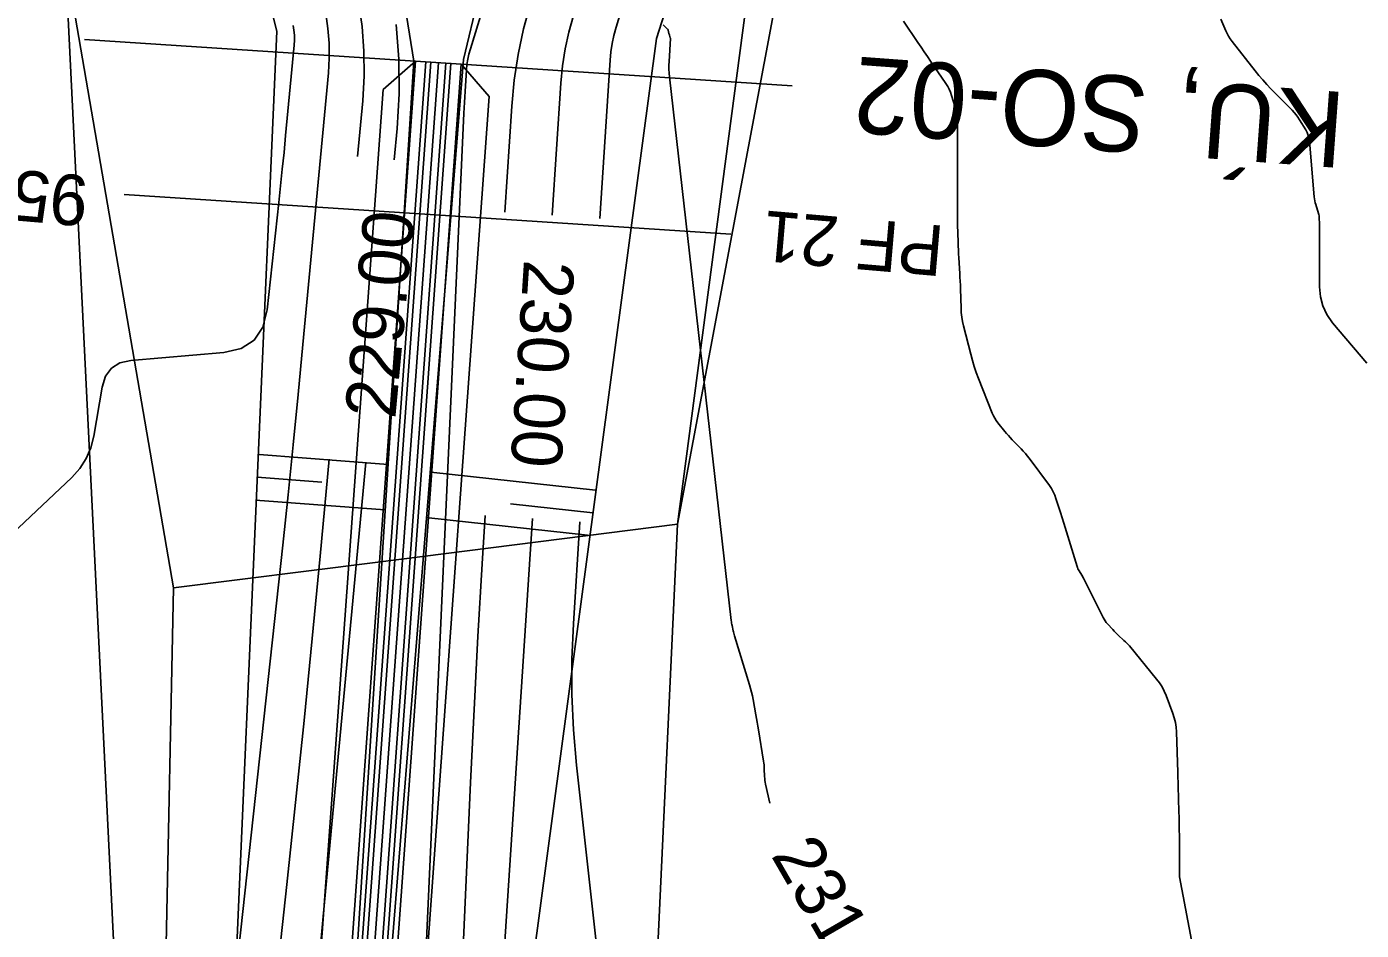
# Model space of a CAD drawing. Extents: x -534410 to -534262, y -1190162 to -1189584.
# Drawn here: x -534369.46 to -534343.12, y -1189644.95 to -1189627.11 of the extents above; entities that cross this region are included whole.
import ezdxf

# ---------------------------------------------------------------- set-up
doc = ezdxf.new("R2010")
doc.units = 0
for name, color, linetype in [('30', 7, 'Continuous'), ('31', 7, 'Continuous'), ('40', 7, 'Continuous'), ('_linie', 7, 'Continuous'), ('_N_osa', 7, 'Continuous'), ('_N_tenká', 7, 'Continuous'), ('_N_tenká_velmi', 7, 'Continuous'), ('_N_text', 7, 'Continuous'), ('_tenka', 7, 'Continuous'), ('_velmi_tenka', 7, 'Continuous'), ('Default', 7, 'Continuous'), ('Hranice parcel', 7, 'Continuous')]:
    doc.layers.add(name, color=color, linetype=linetype)

msp = doc.modelspace()

# ---------------------------------------------------------------- linework, layer by layer
at = {"layer": '30'}
for points in [[(-534357.514, -1189620.943), (-534357.514, -1189620.944), (-534357.5, -1189620.975), (-534357.487, -1189621.008), (-534357.44, -1189621.138), (-534357.431, -1189621.171), (-534357.426, -1189621.204), (-534357.425, -1189621.237), (-534357.429, -1189621.271), (-534357.952, -1189624.26), (-534358.016, -1189624.595), (-534358.09, -1189624.928), (-534358.175, -1189625.258), (-534358.27, -1189625.585), (-534358.669, -1189626.89), (-534358.759, -1189627.218), (-534358.83, -1189627.55), (-534358.881, -1189627.885), (-534358.913, -1189628.224), (-534359.084, -1189630.834)], [(-534361.638, -1189646.761), (-534360.829, -1189628.817), (-534360.824, -1189628.711), (-534360.819, -1189628.604), (-534360.813, -1189628.497), (-534360.806, -1189628.391), (-534360.778, -1189627.965), (-534360.768, -1189627.859), (-534360.752, -1189627.754), (-534360.73, -1189627.65), (-534360.702, -1189627.547), (-534359.197, -1189622.632)], [(-534365.316, -1189645.725), (-534364.406, -1189637.346), (-534364.301, -1189636.356), (-534364.199, -1189635.366), (-534364.1, -1189634.375), (-534364.006, -1189633.383), (-534363.504, -1189628.024), (-534363.486, -1189627.729), (-534363.489, -1189627.436), (-534363.512, -1189627.143), (-534363.555, -1189626.851)], [(-534362.168, -1189627.067), (-534362.114, -1189627.75), (-534362.108, -1189628.435), (-534362.149, -1189629.123), (-534362.207, -1189629.742)], [(-534356.898, -1189627.07), (-534356.802, -1189627.166), (-534356.799, -1189627.168), (-534356.797, -1189627.171), (-534356.796, -1189627.174), (-534356.795, -1189627.178), (-534356.783, -1189627.244), (-534356.781, -1189627.25), (-534356.779, -1189627.255), (-534356.773, -1189627.268), (-534356.771, -1189627.276), (-534356.755, -1189627.329), (-534356.754, -1189627.334), (-534356.753, -1189627.34), (-534356.779, -1189627.795), (-534356.781, -1189627.872), (-534356.781, -1189627.949), (-534356.777, -1189628.025), (-534356.77, -1189628.102), (-534355.551, -1189638.836), (-534355.548, -1189638.861), (-534355.544, -1189638.886), (-534355.54, -1189638.911), (-534355.534, -1189638.936), (-534355.512, -1189639.036), (-534355.507, -1189639.061), (-534355.5, -1189639.086), (-534355.494, -1189639.111), (-534355.486, -1189639.135), (-534355.19, -1189640.102), (-534355.169, -1189640.175), (-534355.15, -1189640.248), (-534355.134, -1189640.322), (-534355.119, -1189640.397), (-534355.066, -1189640.695), (-534355.053, -1189640.77), (-534355.04, -1189640.845), (-534355.028, -1189640.919), (-534355.015, -1189640.994), (-534354.914, -1189641.61), (-534354.909, -1189641.648), (-534354.904, -1189641.686), (-534354.901, -1189641.724), (-534354.899, -1189641.762), (-534354.893, -1189641.915), (-534354.891, -1189641.953), (-534354.887, -1189641.991), (-534354.881, -1189642.029), (-534354.874, -1189642.066), (-534354.791, -1189642.439)], [(-534343.005, -1189633.752), (-534343.681, -1189632.954), (-534343.794, -1189632.795), (-534343.875, -1189632.624), (-534343.924, -1189632.441), (-534343.94, -1189632.246), (-534343.94, -1189631.091), (-534343.94, -1189631.066), (-534343.941, -1189631.042), (-534343.941, -1189631.017), (-534343.942, -1189630.992), (-534343.945, -1189630.894), (-534343.947, -1189630.869), (-534343.95, -1189630.845), (-534343.955, -1189630.821), (-534343.961, -1189630.797), (-534344.015, -1189630.623), (-534344.026, -1189630.586), (-534344.034, -1189630.548), (-534344.041, -1189630.511), (-534344.045, -1189630.472), (-534344.14, -1189629.37), (-534344.148, -1189629.312), (-534344.163, -1189629.255), (-534344.184, -1189629.201), (-534344.212, -1189629.149), (-534344.336, -1189628.946), (-534344.369, -1189628.896), (-534344.404, -1189628.849), (-534344.442, -1189628.803), (-534344.482, -1189628.76), (-534344.899, -1189628.336), (-534344.981, -1189628.25), (-534345.06, -1189628.162), (-534345.137, -1189628.072), (-534345.212, -1189627.98), (-534345.666, -1189627.402), (-534345.703, -1189627.352), (-534345.736, -1189627.3), (-534345.765, -1189627.245), (-534345.791, -1189627.189), (-534345.887, -1189626.959)], [(-534362.766, -1189635.716), (-534363.58, -1189644.397), (-534363.668, -1189645.326), (-534363.76, -1189646.254), (-534363.856, -1189647.182), (-534363.955, -1189648.109), (-534364.357, -1189651.819), (-534364.456, -1189652.746), (-534364.55, -1189653.674), (-534364.64, -1189654.602), (-534364.726, -1189655.531), (-534365.346, -1189662.432), (-534365.472, -1189663.892), (-534365.591, -1189665.352), (-534365.7, -1189666.814), (-534365.801, -1189668.276), (-534366.596, -1189680.297)], [(-534359.474, -1189636.822), (-534360.283, -1189649.202)]]:
    msp.add_lwpolyline(points, dxfattribs=at)
at = {"layer": '31'}
for points in [[(-534358.147, -1189630.895), (-534357.942, -1189627.768), (-534357.927, -1189627.604), (-534357.902, -1189627.442), (-534357.868, -1189627.281), (-534357.824, -1189627.122), (-534357.631, -1189626.49), (-534357.585, -1189626.331), (-534357.544, -1189626.171), (-534357.508, -1189626.01), (-534357.477, -1189625.848), (-534356.628, -1189621), (-534356.625, -1189620.976), (-534356.626, -1189620.953), (-534356.629, -1189620.929), (-534356.636, -1189620.907), (-534356.669, -1189620.816), (-534356.678, -1189620.793), (-534356.687, -1189620.771), (-534356.688, -1189620.771)], [(-534362.929, -1189629.674), (-534362.826, -1189628.573), (-534362.797, -1189628.082), (-534362.802, -1189627.593), (-534362.84, -1189627.105), (-534362.912, -1189626.619), (-534363.334, -1189624.309), (-534363.39, -1189624.007), (-534363.45, -1189623.706), (-534363.512, -1189623.405), (-534363.576, -1189623.105), (-534363.953, -1189621.395), (-534363.959, -1189621.351), (-534363.959, -1189621.308), (-534363.952, -1189621.265), (-534363.938, -1189621.222), (-534363.868, -1189621.054), (-534363.848, -1189621.013), (-534363.826, -1189620.975), (-534363.823, -1189620.971)], [(-534358.341, -1189621.116), (-534358.34, -1189621.117), (-534358.322, -1189621.158), (-534358.306, -1189621.2), (-534358.245, -1189621.369), (-534358.232, -1189621.412), (-534358.226, -1189621.455), (-534358.225, -1189621.498), (-534358.23, -1189621.542), (-534358.508, -1189623.132), (-534358.561, -1189623.411), (-534358.623, -1189623.687), (-534358.693, -1189623.962), (-534358.772, -1189624.235), (-534359.514, -1189626.658), (-534359.65, -1189627.155), (-534359.758, -1189627.658), (-534359.835, -1189628.166), (-534359.884, -1189628.679), (-534360.021, -1189630.773)], [(-534364.198, -1189627.084), (-534364.184, -1189627.181), (-534364.176, -1189627.279), (-534364.175, -1189627.376), (-534364.181, -1189627.475), (-534364.349, -1189629.261), (-534364.38, -1189629.592), (-534364.413, -1189629.922), (-534364.447, -1189630.252), (-534364.482, -1189630.582), (-534364.712, -1189632.702), (-534364.797, -1189633.044), (-534364.968, -1189633.297), (-534365.226, -1189633.463), (-534365.569, -1189633.541), (-534367.402, -1189633.701), (-534367.62, -1189633.749), (-534367.788, -1189633.853), (-534367.905, -1189634.012), (-534367.971, -1189634.226), (-534368.133, -1189635.192), (-534368.19, -1189635.425), (-534368.283, -1189635.639), (-534368.409, -1189635.834), (-534368.571, -1189636.011), (-534371.025, -1189638.319)], [(-534346.466, -1189645.149), (-534346.704, -1189643.898), (-534346.706, -1189643.889), (-534346.707, -1189643.88), (-534346.707, -1189643.871), (-534346.707, -1189643.862), (-534346.707, -1189643.791), (-534346.707, -1189643.086), (-534346.708, -1189642.965), (-534346.709, -1189642.845), (-534346.712, -1189642.724), (-534346.715, -1189642.604), (-534346.738, -1189641.853), (-534346.738, -1189641.836), (-534346.764, -1189641.033), (-534346.771, -1189640.94), (-534346.785, -1189640.847), (-534346.807, -1189640.757), (-534346.836, -1189640.668), (-534346.969, -1189640.314), (-534347.006, -1189640.227), (-534347.049, -1189640.145), (-534347.099, -1189640.066), (-534347.156, -1189639.991), (-534347.694, -1189639.337), (-534347.719, -1189639.308), (-534347.745, -1189639.28), (-534347.772, -1189639.253), (-534347.8, -1189639.226), (-534347.913, -1189639.123), (-534347.942, -1189639.097), (-534347.969, -1189639.07), (-534347.996, -1189639.043), (-534348.022, -1189639.015), (-534348.125, -1189638.901), (-534348.149, -1189638.872), (-534348.172, -1189638.842), (-534348.192, -1189638.809), (-534348.211, -1189638.776), (-534348.587, -1189638.023), (-534348.598, -1189638.001), (-534348.609, -1189637.98), (-534348.622, -1189637.958), (-534348.634, -1189637.938), (-534348.685, -1189637.854), (-534348.698, -1189637.833), (-534348.708, -1189637.811), (-534348.718, -1189637.789), (-534348.726, -1189637.766), (-534348.99, -1189636.914), (-534349.055, -1189636.705), (-534349.142, -1189636.426), (-534349.166, -1189636.358), (-534349.196, -1189636.292), (-534349.231, -1189636.229), (-534349.272, -1189636.169), (-534349.671, -1189635.629), (-534349.708, -1189635.581), (-534349.746, -1189635.534), (-534349.787, -1189635.489), (-534349.828, -1189635.445), (-534350.007, -1189635.264), (-534350.045, -1189635.224), (-534350.082, -1189635.184), (-534350.118, -1189635.143), (-534350.153, -1189635.1), (-534350.29, -1189634.93), (-534350.323, -1189634.886), (-534350.352, -1189634.84), (-534350.377, -1189634.793), (-534350.399, -1189634.743), (-534350.67, -1189634.059), (-534350.715, -1189633.941), (-534350.756, -1189633.822), (-534350.793, -1189633.701), (-534350.826, -1189633.579), (-534350.968, -1189633.017), (-534350.988, -1189632.93), (-534351.002, -1189632.843), (-534351.012, -1189632.755), (-534351.017, -1189632.667), (-534351.028, -1189632.288), (-534351.03, -1189632.211), (-534351.033, -1189632.134), (-534351.037, -1189632.057), (-534351.041, -1189631.98), (-534351.059, -1189631.673), (-534351.064, -1189631.596), (-534351.067, -1189631.519), (-534351.07, -1189631.442), (-534351.073, -1189631.365), (-534351.084, -1189631.013), (-534351.086, -1189630.929), (-534351.088, -1189630.844), (-534351.089, -1189630.76), (-534351.089, -1189630.676), (-534351.089, -1189628.976), (-534351.091, -1189628.911), (-534351.098, -1189628.846), (-534351.11, -1189628.782), (-534351.127, -1189628.719), (-534351.202, -1189628.467), (-534351.223, -1189628.405), (-534351.249, -1189628.345), (-534351.279, -1189628.288), (-534351.314, -1189628.233), (-534351.617, -1189627.792), (-534351.68, -1189627.7), (-534351.743, -1189627.609), (-534351.805, -1189627.517), (-534351.867, -1189627.425), (-534352.15, -1189627.003)], [(-534365.291, -1189652.963), (-534364.324, -1189644.049), (-534364.151, -1189642.43), (-534363.984, -1189640.809), (-534363.824, -1189639.189), (-534363.669, -1189637.567), (-534363.489, -1189635.648)], [(-534360.41, -1189636.76), (-534360.47, -1189637.715), (-534360.553, -1189639.153), (-534360.629, -1189640.593), (-534360.697, -1189642.032), (-534361.011, -1189648.981), (-534361.079, -1189650.619), (-534361.135, -1189652.258), (-534361.181, -1189653.897), (-534361.215, -1189655.536), (-534361.422, -1189667.638), (-534361.413, -1189668.597), (-534361.351, -1189669.551), (-534361.238, -1189670.5), (-534361.072, -1189671.445), (-534359.975, -1189676.838)], [(-534358.205, -1189645.301), (-534358.606, -1189641.691), (-534358.668, -1189640.994), (-534358.699, -1189640.296), (-534358.699, -1189639.597), (-534358.669, -1189638.898), (-534358.538, -1189636.883)]]:
    msp.add_lwpolyline(points, dxfattribs=at)
at = {"layer": '_linie'}
for points in [[(-534366.12, -1189620.81), (-534364.52, -1189627.2), (-534365.69, -1189653.8), (-534366.76, -1189684.81), (-534368.14, -1189748.73), (-534368.38, -1189779.14), (-534368.65, -1189820.64), (-534368.59, -1189847.58), (-534367.2, -1189913.8)], [(-534363.12, -1189621.02), (-534362.79, -1189621.58), (-534361.82, -1189627.79), (-534363.46, -1189653.55), (-534365.47, -1189684.77), (-534366.65, -1189748.83), (-534366.75, -1189779.47), (-534366.9, -1189820.47), (-534366.95, -1189846.72), (-534366.338, -1189888.804), (-534363.85, -1189911.95), (-534357.07, -1189929.19), (-534352.334, -1189940.856)], [(-534359.03, -1189621.26), (-534359.41, -1189621.83), (-534360.84, -1189627.76), (-534362.92, -1189653.56), (-534364.64, -1189685), (-534365.94, -1189748.9), (-534366.02, -1189779.52), (-534366.03, -1189820.5), (-534366.48, -1189846.73), (-534365.511, -1189888.873), (-534362.72, -1189912.12), (-534356.62, -1189928.64), (-534351.589, -1189940.594)]]:
    msp.add_lwpolyline(points, dxfattribs=at)
at = {"layer": '_N_osa'}
msp.add_lwpolyline([(-534351.95, -1189940.722), (-534356.845, -1189928.915), (-534363.285, -1189912.035), (-534365.925, -1189888.838), (-534366.715, -1189846.725), (-534366.465, -1189820.485), (-534366.385, -1189779.495), (-534366.295, -1189748.865), (-534365.055, -1189684.885), (-534363.19, -1189653.555), (-534361.333, -1189627.822)], dxfattribs=at)
at = {"layer": '_N_tenká'}
msp.add_line((-534354.347, -1189628.277), (-534368.317, -1189627.366), dxfattribs=at)
for points in [[(-534352.92, -1189941.124), (-534357.821, -1189929.303), (-534364.313, -1189912.285), (-534366.973, -1189888.908), (-534367.765, -1189846.73), (-534367.515, -1189820.479), (-534367.435, -1189779.492), (-534367.345, -1189748.853), (-534366.104, -1189684.844), (-534364.238, -1189653.486), (-534362.424, -1189628.352), (-534361.782, -1189627.792)], [(-534352.089, -1189940.779), (-534356.984, -1189928.97), (-534363.432, -1189912.071), (-534366.074, -1189888.848), (-534366.865, -1189846.726), (-534366.615, -1189820.484), (-534366.535, -1189779.495), (-534366.445, -1189748.863), (-534365.205, -1189684.879), (-534363.34, -1189653.545), (-534361.483, -1189627.812)], [(-534351.812, -1189940.664), (-534356.706, -1189928.86), (-534363.138, -1189911.999), (-534365.775, -1189888.828), (-534366.565, -1189846.724), (-534366.315, -1189820.486), (-534366.235, -1189779.495), (-534366.145, -1189748.867), (-534364.905, -1189684.891), (-534363.04, -1189653.565), (-534361.184, -1189627.831)], [(-534350.98, -1189940.319), (-534355.869, -1189928.527), (-534362.257, -1189911.785), (-534364.876, -1189888.769), (-534365.665, -1189846.72), (-534365.415, -1189820.491), (-534365.335, -1189779.498), (-534365.245, -1189748.877), (-534364.006, -1189684.926), (-534362.142, -1189653.624), (-534360.329, -1189628.488), (-534360.884, -1189627.851)]]:
    msp.add_lwpolyline(points, dxfattribs=at)
at = {"layer": '_N_tenká_velmi'}
for points in [[(-534352.366, -1189940.894), (-534357.263, -1189929.081), (-534363.726, -1189912.142), (-534366.374, -1189888.868), (-534367.165, -1189846.727), (-534366.915, -1189820.482), (-534366.835, -1189779.494), (-534366.745, -1189748.86), (-534365.505, -1189684.867), (-534363.639, -1189653.525), (-534361.782, -1189627.792)], [(-534352.181, -1189940.817), (-534357.077, -1189929.007), (-534363.53, -1189912.095), (-534366.174, -1189888.855), (-534366.965, -1189846.726), (-534366.715, -1189820.484), (-534366.635, -1189779.494), (-534366.545, -1189748.862), (-534365.305, -1189684.875), (-534363.439, -1189653.539), (-534361.583, -1189627.805)], [(-534351.719, -1189940.626), (-534356.613, -1189928.823), (-534363.04, -1189911.975), (-534365.675, -1189888.822), (-534366.465, -1189846.724), (-534366.215, -1189820.486), (-534366.135, -1189779.496), (-534366.045, -1189748.868), (-534364.805, -1189684.895), (-534362.941, -1189653.571), (-534361.084, -1189627.838)], [(-534351.534, -1189940.549), (-534356.427, -1189928.749), (-534362.844, -1189911.928), (-534365.475, -1189888.808), (-534366.265, -1189846.723), (-534366.015, -1189820.488), (-534365.935, -1189779.496), (-534365.845, -1189748.87), (-534364.605, -1189684.903), (-534362.741, -1189653.585), (-534360.884, -1189627.851)]]:
    msp.add_lwpolyline(points, dxfattribs=at)
at = {"layer": '_N_text'}
msp.add_lwpolyline([(-534355.562, -1189631.204), (-534367.537, -1189630.423)], dxfattribs=at)
at = {"layer": '_tenka'}
for points in [[(-534349.13, -1189939.73), (-534354.63, -1189926.96), (-534362.03, -1189907.65), (-534364.521, -1189888.74), (-534364.47, -1189846.64), (-534364.29, -1189820.63), (-534364.22, -1189780.69), (-534363.18, -1189749.38), (-534362.5, -1189685.39), (-534360.27, -1189651.6), (-534357.03, -1189627.34), (-534354.77, -1189620.37)], [(-534366.12, -1189620.81), (-534364.52, -1189627.2), (-534365.69, -1189653.8), (-534366.76, -1189684.81), (-534368.14, -1189748.73), (-534368.38, -1189779.14), (-534368.65, -1189820.64), (-534368.59, -1189847.58), (-534367.2, -1189913.8)], [(-534366.12, -1189620.81), (-534364.52, -1189627.2), (-534365.69, -1189653.8), (-534366.76, -1189684.81), (-534368.14, -1189748.73), (-534368.38, -1189779.14), (-534368.65, -1189820.64), (-534368.59, -1189847.58), (-534367.2, -1189913.8)], [(-534363.12, -1189621.02), (-534362.79, -1189621.58), (-534361.82, -1189627.79), (-534363.46, -1189653.55), (-534365.47, -1189684.77), (-534366.65, -1189748.83), (-534366.75, -1189779.47), (-534366.9, -1189820.47), (-534366.95, -1189846.72), (-534366.338, -1189888.804), (-534363.85, -1189911.95), (-534357.07, -1189929.19), (-534352.334, -1189940.856)], [(-534363.12, -1189621.02), (-534362.79, -1189621.58), (-534361.82, -1189627.79), (-534363.46, -1189653.55), (-534365.47, -1189684.77), (-534366.65, -1189748.83), (-534366.75, -1189779.47), (-534366.9, -1189820.47), (-534366.95, -1189846.72), (-534366.338, -1189888.804), (-534363.85, -1189911.95), (-534357.07, -1189929.19), (-534352.334, -1189940.856)], [(-534359.03, -1189621.26), (-534359.41, -1189621.83), (-534360.84, -1189627.76), (-534362.92, -1189653.56), (-534364.64, -1189685), (-534365.94, -1189748.9), (-534366.02, -1189779.52), (-534366.03, -1189820.5), (-534366.48, -1189846.73), (-534365.511, -1189888.873), (-534362.72, -1189912.12), (-534356.62, -1189928.64), (-534351.589, -1189940.594)], [(-534359.03, -1189621.26), (-534359.41, -1189621.83), (-534360.84, -1189627.76), (-534362.92, -1189653.56), (-534364.64, -1189685), (-534365.94, -1189748.9), (-534366.02, -1189779.52), (-534366.03, -1189820.5), (-534366.48, -1189846.73), (-534365.511, -1189888.873), (-534362.72, -1189912.12), (-534356.62, -1189928.64), (-534351.589, -1189940.594)], [(-534368.65, -1189626.81), (-534368.65, -1189626.81), (-534367.31, -1189654.04), (-534367.67, -1189685.23), (-534369.56, -1189748.93), (-534369.48, -1189778.6), (-534369.45, -1189820.62), (-534369.45, -1189847.87), (-534371.206, -1189896.071), (-534372.39, -1189914.47)]]:
    msp.add_lwpolyline(points, dxfattribs=at)
at = {"layer": '_velmi_tenka'}
for p, q in [((-534364.873, -1189635.559), (-534362.321, -1189635.753)), ((-534364.907, -1189636.007), (-534363.631, -1189636.104)), ((-534358.232, -1189636.264), (-534361.483, -1189635.905)), ((-534364.942, -1189636.456), (-534362.39, -1189636.65)), ((-534358.282, -1189636.711), (-534359.907, -1189636.532)), ((-534358.331, -1189637.159), (-534361.582, -1189636.799))]:
    msp.add_line(p, q, dxfattribs=at)
at = {"layer": 'Default'}
msp.add_line((-534368.65, -1189626.81), (-534367.31, -1189654.04), dxfattribs=at)
msp.add_lwpolyline([(-534349.13, -1189939.73), (-534354.63, -1189926.96), (-534362.03, -1189907.65), (-534364.521, -1189888.74), (-534364.47, -1189846.64), (-534364.29, -1189820.63), (-534364.22, -1189780.69), (-534363.18, -1189749.38), (-534362.5, -1189685.39), (-534360.27, -1189651.6), (-534357.03, -1189627.34), (-534354.77, -1189620.37)], dxfattribs=at)
at = {"layer": 'Hranice parcel'}
for p, q in [((-534366.56, -1189638.19), (-534368.76, -1189625.38)), ((-534359.48, -1189697.97), (-534356.61, -1189636.93)), ((-534366.56, -1189638.19), (-534367.77, -1189697.34))]:
    msp.add_line(p, q, dxfattribs=at)
for points in [[(-534356.61, -1189636.93), (-534352.14, -1189603.1), (-534349.757, -1189584.47)], [(-534347.83, -1189584.47), (-534354.43, -1189625.3), (-534356.61, -1189636.93)], [(-534366.56, -1189638.19), (-534362.58, -1189637.69), (-534356.61, -1189636.93)]]:
    msp.add_lwpolyline(points, dxfattribs=at)

# ---------------------------------------------------------------- texts
at = {"layer": '40'}
for s, rotation, p in [('229.00', 84.6494, (-534362.185, -1189634.869)), ('230.00', 266.2644, (-534359.641, -1189631.698)), ('231.00', 300.0371, (-534354.779, -1189643.469))]:
    msp.add_text(s, height=1, rotation=rotation, dxfattribs=at).set_placement(p)
at = {"layer": '_N_text'}
for s, height, rotation, p in [('KÚ, SO-02', 1.5, 175.8075, (-534343.402, -1189628.407)), ('950', 1, 175.0404, (-534368.21, -1189630.061)), ('PF 21', 1, 175.0879, (-534351.324, -1189631.044))]:
    msp.add_text(s, height=height, rotation=rotation, dxfattribs=at).set_placement(p)

doc.saveas('drawing.dxf')
